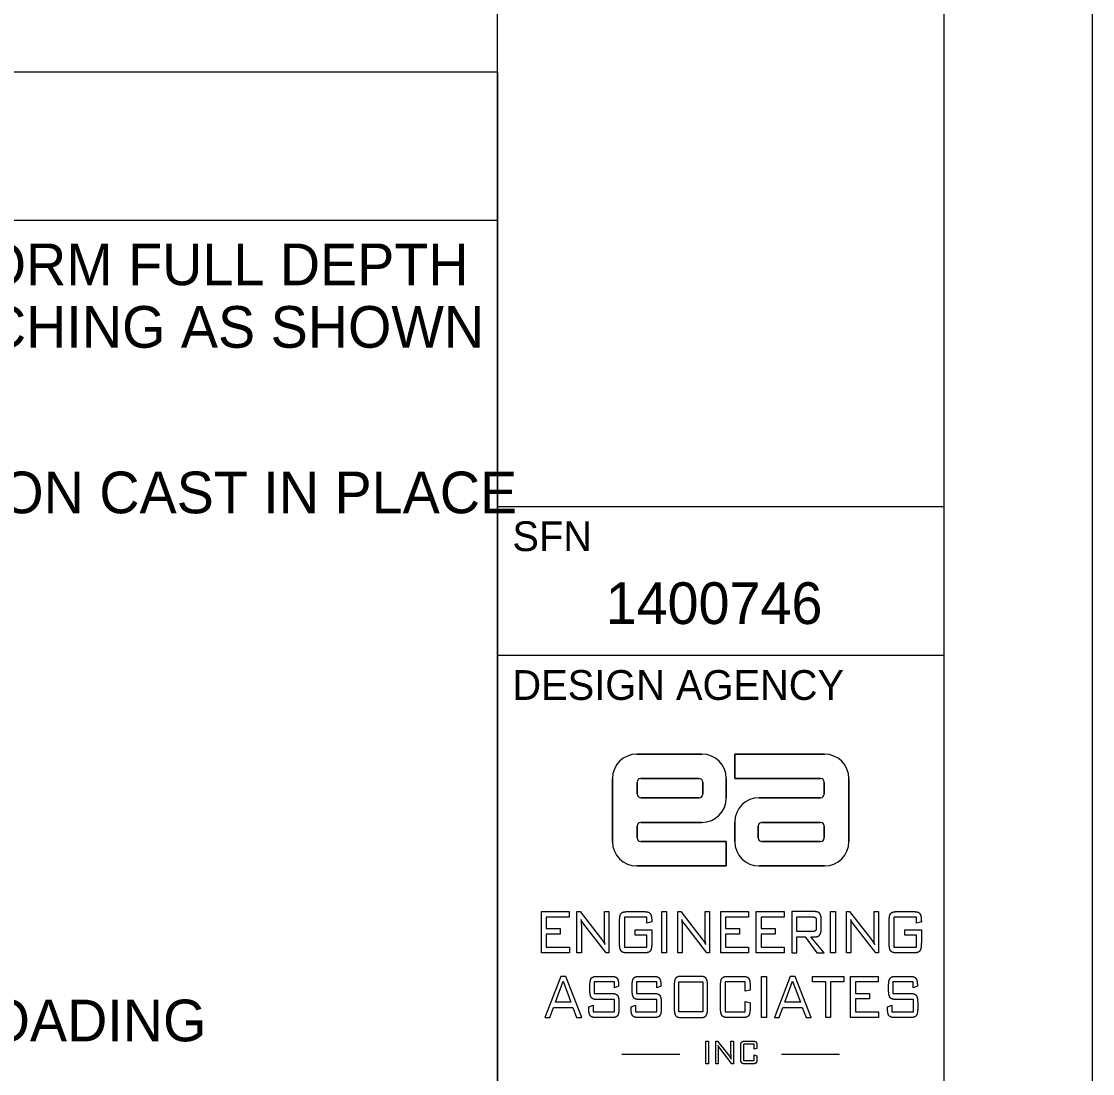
# Model space of a CAD drawing. Extents: x 0 to 680, y -49 to 440.
# Drawn here: x 608 to 680, y 71.9 to 142.6 of the extents above; entities that cross this region are included whole.
import ezdxf

# ---------------------------------------------------------------- set-up
doc = ezdxf.new("R2010")
doc.units = 0
for name, color, linetype in [('SN_X_Public', 7, 'Continuous'), ('SV_X_Shot_Marker', 7, 'Continuous'), ('UT_X_Misc_Cells', 7, 'Continuous'), ('UT_X_Telecom_Cells', 7, 'Continuous'), ('VG_X_Cells', 7, 'Continuous')]:
    doc.layers.add(name, color=color, linetype=linetype)

msp = doc.modelspace()

# ---------------------------------------------------------------- linework, layer by layer
at = {"layer": 'SV_X_Shot_Marker'}
for p, q in [((640, 10), (640, 430)), ((640, 110), (670, 110)), ((640, 100), (670, 100))]:
    msp.add_line(p, q, dxfattribs=at)
msp.add_lwpolyline([(30, 430), (670, 430), (670, 10), (30, 10)], close=True, dxfattribs=at)
at = {"layer": 'UT_X_Misc_Cells'}
for p, q in [((640, 129.205), (495, 129.205)), ((655, 80), (655, 80))]:
    msp.add_line(p, q, dxfattribs=at)
msp.add_lwpolyline([(495, 139.205), (640, 139.205), (640, 13.27), (495, 13.27)], close=True, dxfattribs=at)
at = {"layer": 'UT_X_Telecom_Cells'}
for p, q in [((653.737, 93.354), (649.367, 93.354)), ((649.367, 93.354), (653.737, 93.354)), ((655.947, 93.354), (661.978, 93.354)), ((655.947, 91.713), (655.947, 93.354)), ((647.726, 91.713), (647.726, 87.482)), ((647.726, 87.482), (647.726, 91.713)), ((649.387, 90.665), (649.387, 91.475)), ((649.387, 91.475), (649.387, 90.665)), ((649.624, 91.713), (653.559, 91.713)), ((653.559, 91.713), (649.624, 91.713)), ((653.797, 91.475), (653.797, 90.665)), ((653.797, 90.665), (653.797, 91.475)), ((655.378, 90.408), (655.378, 91.713)), ((655.378, 91.713), (655.378, 90.408)), ((661.721, 91.713), (655.947, 91.713)), ((661.958, 91.475), (661.958, 90.665)), ((661.958, 90.665), (661.958, 91.475)), ((663.619, 87.482), (663.619, 91.713)), ((663.619, 91.713), (663.619, 87.482)), ((653.559, 90.428), (649.624, 90.428)), ((649.624, 90.428), (653.559, 90.428)), ((661.721, 90.428), (657.588, 90.428)), ((657.588, 90.428), (661.721, 90.428)), ((649.624, 88.767), (653.737, 88.767)), ((653.737, 88.767), (649.624, 88.767)), ((655.947, 88.786), (655.947, 87.482)), ((655.947, 87.482), (655.947, 88.786)), ((657.766, 88.767), (661.721, 88.767)), ((661.721, 88.767), (657.766, 88.767)), ((649.387, 87.719), (649.387, 88.529)), ((649.387, 88.529), (649.387, 87.719)), ((657.529, 87.719), (657.529, 88.529)), ((657.529, 88.529), (657.529, 87.719)), ((661.958, 88.529), (661.958, 87.719)), ((661.958, 87.719), (661.958, 88.529)), ((649.624, 87.482), (655.378, 87.482)), ((655.378, 87.482), (655.378, 85.84)), ((661.721, 87.482), (657.766, 87.482)), ((657.766, 87.482), (661.721, 87.482)), ((655.378, 85.84), (649.367, 85.84)), ((657.588, 85.84), (661.978, 85.84)), ((661.978, 85.84), (657.588, 85.84)), ((648.203, 80.655), (648.203, 82.113)), ((648.658, 82.768), (649.911, 82.768)), ((661.43, 82.124), (661.43, 81.72)), ((661.758, 81.612), (661.758, 82.232)), ((666.325, 80.655), (666.325, 82.113)), ((666.78, 82.768), (668.034, 82.768)), ((649.911, 80), (648.658, 80)), ((668.034, 80), (666.78, 80)), ((646.656, 78.418), (647.686, 78.418)), ((649.501, 78.418), (650.531, 78.418)), ((653.669, 78.418), (652.329, 78.418)), ((655.445, 78.418), (656.528, 78.418)), ((666.739, 78.418), (667.769, 78.418)), ((646.205, 77.523), (646.205, 77.764)), ((649.049, 77.523), (649.049, 77.764)), ((651.874, 77.764), (651.874, 76.305)), ((654.12, 76.305), (654.12, 77.764)), ((654.99, 76.305), (654.99, 77.764)), ((666.288, 77.523), (666.288, 77.764)), ((648.164, 76.616), (648.164, 76.305)), ((651.008, 76.616), (651.008, 76.305)), ((668.246, 76.616), (668.246, 76.305)), ((647.714, 75.65), (646.585, 75.65)), ((650.558, 75.65), (649.429, 75.65)), ((652.329, 75.65), (653.669, 75.65)), ((656.528, 75.65), (655.445, 75.65)), ((667.796, 75.65), (666.668, 75.65)), ((656.347, 72.906), (656.347, 73.709)), ((656.597, 74.069), (657.193, 74.069)), ((648.359, 73.19), (652.263, 73.19)), ((659.08, 73.19), (662.985, 73.19)), ((657.193, 72.546), (656.597, 72.546))]:
    msp.add_line(p, q, dxfattribs=at)
for points in [[(661.978, 93.354), (655.947, 93.354), (655.947, 91.713), (661.721, 91.713)], [(649.367, 85.84), (655.378, 85.84), (655.378, 87.482), (649.624, 87.482)], [(645.638, 81.631), (645.638, 80), (645.342, 80), (645.342, 82.768), (645.545, 82.768), (646.995, 80.917)], [(647.186, 81.249), (647.186, 82.768), (647.482, 82.768), (647.482, 80), (647.3, 80), (645.812, 81.925)], [(650.366, 82.145), (650.366, 82.076), (650.043, 81.985), (650.043, 82.391), (648.526, 82.391), (648.526, 80.385), (650.043, 80.385), (650.043, 81.198), (649.26, 81.198), (649.26, 81.551), (650.366, 81.551), (650.366, 80.655)], [(652.408, 81.631), (652.408, 80), (652.112, 80), (652.112, 82.768), (652.315, 82.768), (653.765, 80.917)], [(653.956, 81.249), (653.956, 82.768), (654.252, 82.768), (654.252, 80), (654.071, 80), (652.582, 81.925)], [(661.347, 82.768), (659.786, 82.768), (659.786, 80), (660.111, 80), (660.111, 81.078), (660.681, 81.078), (661.469, 80), (661.949, 80), (661.063, 81.078), (661.347, 81.078)], [(661.221, 81.436), (660.111, 81.436), (660.111, 82.41), (661.221, 82.41)], [(663.76, 81.631), (663.76, 80), (663.464, 80), (663.464, 82.768), (663.668, 82.768), (665.117, 80.917)], [(665.308, 81.249), (665.308, 82.768), (665.604, 82.768), (665.604, 80), (665.423, 80), (663.935, 81.925)], [(668.489, 82.145), (668.489, 82.076), (668.166, 81.985), (668.166, 82.391), (666.648, 82.391), (666.648, 80.385), (668.166, 80.385), (668.166, 81.198), (667.382, 81.198), (667.382, 81.551), (668.489, 81.551), (668.489, 80.655)], [(648.141, 77.811), (648.141, 77.753), (647.864, 77.64), (647.864, 78.042), (646.496, 78.042), (646.496, 77.269), (647.714, 77.269)], [(650.985, 77.811), (650.985, 77.753), (650.708, 77.64), (650.708, 78.042), (649.34, 78.042), (649.34, 77.269), (650.558, 77.269)], [(656.979, 77.764), (656.979, 77.503), (656.654, 77.416), (656.654, 78.042), (655.313, 78.042), (655.313, 76.035), (656.654, 76.035), (656.654, 76.729), (656.979, 76.632), (656.979, 76.305)], [(668.223, 77.811), (668.223, 77.753), (667.946, 77.64), (667.946, 78.042), (666.578, 78.042), (666.578, 77.269), (667.796, 77.269)], [(646.131, 76.305), (646.131, 76.381), (646.431, 76.48), (646.431, 76.035), (647.873, 76.035), (647.873, 76.868), (646.656, 76.868)], [(648.975, 76.305), (648.975, 76.381), (649.275, 76.48), (649.275, 76.035), (650.717, 76.035), (650.717, 76.868), (649.501, 76.868)], [(666.213, 76.305), (666.213, 76.381), (666.513, 76.48), (666.513, 76.035), (667.956, 76.035), (667.956, 76.868), (666.739, 76.868)], [(654.842, 73.443), (654.842, 72.546), (654.68, 72.546), (654.68, 74.069), (654.791, 74.069), (655.589, 73.05)], [(655.694, 73.233), (655.694, 74.069), (655.857, 74.069), (655.857, 72.546), (655.757, 72.546), (654.938, 73.605)], [(657.441, 73.709), (657.441, 73.565), (657.262, 73.518), (657.262, 73.861), (656.525, 73.861), (656.525, 72.758), (657.262, 72.758), (657.262, 73.139), (657.441, 73.086), (657.441, 72.906)]]:
    msp.add_lwpolyline(points, dxfattribs=at)
for points in [[(642.948, 80), (642.948, 82.768), (644.813, 82.768), (644.813, 82.397), (643.273, 82.397), (643.273, 81.627), (644.215, 81.627), (644.215, 81.261), (643.273, 81.261), (643.273, 80.379), (644.829, 80.379), (644.829, 80)], [(651.039, 80), (651.039, 82.768), (651.364, 82.768), (651.364, 80)], [(655, 80), (655, 82.768), (656.865, 82.768), (656.865, 82.397), (655.325, 82.397), (655.325, 81.627), (656.267, 81.627), (656.267, 81.261), (655.325, 81.261), (655.325, 80.379), (656.88, 80.379), (656.88, 80)], [(657.393, 80), (657.393, 82.768), (659.258, 82.768), (659.258, 82.397), (657.718, 82.397), (657.718, 81.627), (658.66, 81.627), (658.66, 81.261), (657.718, 81.261), (657.718, 80.379), (659.273, 80.379), (659.273, 80)], [(662.391, 80), (662.391, 82.768), (662.716, 82.768), (662.716, 80)], [(643.191, 75.65), (643.51, 75.65), (643.757, 76.333), (645.068, 76.333), (645.315, 75.65), (645.671, 75.65), (644.595, 78.418), (644.249, 78.418)], [(643.893, 76.685), (644.413, 78.101), (644.936, 76.685)], [(652.197, 76.035), (652.197, 78.042), (653.801, 78.042), (653.801, 76.035)], [(657.746, 75.65), (657.746, 78.418), (658.071, 78.418), (658.071, 75.65)], [(658.611, 75.65), (658.93, 75.65), (659.177, 76.333), (660.488, 76.333), (660.736, 75.65), (661.091, 75.65), (660.015, 78.418), (659.669, 78.418)], [(659.313, 76.685), (659.834, 78.101), (660.356, 76.685)], [(662.384, 78.042), (662.384, 75.65), (662.061, 75.65), (662.061, 78.042), (661.176, 78.042), (661.176, 78.418), (663.272, 78.418), (663.272, 78.042)], [(663.732, 75.65), (663.732, 78.418), (665.597, 78.418), (665.597, 78.047), (664.057, 78.047), (664.057, 77.277), (664.999, 77.277), (664.999, 76.911), (664.057, 76.911), (664.057, 76.03), (665.612, 76.03), (665.612, 75.65)], [(653.996, 72.546), (653.996, 74.069), (654.175, 74.069), (654.175, 72.546)]]:
    msp.add_lwpolyline(points, close=True, dxfattribs=at)
for centre, radius, start, end in [((649.367, 91.713), 1.641, 90, 180), ((649.367, 91.713), 1.641, 90, 180), ((653.737, 91.713), 1.641, 0, 90), ((653.737, 91.713), 1.641, 0, 90), ((661.978, 91.713), 1.641, 0, 90), ((661.978, 91.713), 1.641, 0, 90), ((649.624, 91.475), 0.237, 90, 180), ((649.624, 91.475), 0.237, 90, 180), ((653.559, 91.475), 0.237, 0, 90), ((653.559, 91.475), 0.237, 0, 90), ((661.721, 91.475), 0.237, 0, 90), ((661.721, 91.475), 0.237, 0, 90), ((649.624, 90.665), 0.237, 180, 270), ((649.624, 90.665), 0.237, 180, 270), ((653.559, 90.665), 0.237, 270, 0), ((653.559, 90.665), 0.237, 270, 0), ((653.737, 90.408), 1.641, 270, 360), ((653.737, 90.408), 1.641, 270, 360), ((657.588, 88.786), 1.641, 90, 180), ((657.588, 88.786), 1.641, 90, 180), ((661.721, 90.665), 0.237, 270, 0), ((661.721, 90.665), 0.237, 270, 0), ((649.624, 88.529), 0.237, 90, 180), ((649.624, 88.529), 0.237, 90, 180), ((657.766, 88.529), 0.237, 90, 180), ((657.766, 88.529), 0.237, 90, 180), ((661.721, 88.529), 0.237, 0, 90), ((661.721, 88.529), 0.237, 0, 90), ((649.367, 87.482), 1.641, 180, 270), ((649.367, 87.482), 1.641, 180, 270), ((649.624, 87.719), 0.237, 180, 270), ((649.624, 87.719), 0.237, 180, 270), ((657.588, 87.482), 1.641, 180, 270), ((657.588, 87.482), 1.641, 180, 270), ((657.766, 87.719), 0.237, 180, 270), ((657.766, 87.719), 0.237, 180, 270), ((661.721, 87.719), 0.237, 270, 0), ((661.721, 87.719), 0.237, 270, 0), ((661.978, 87.482), 1.641, 270, 360), ((661.978, 87.482), 1.641, 270, 360)]:
    msp.add_arc(centre, radius, start, end, dxfattribs=at)
for points in [[(645.779, 81.967), (645.669, 82.108), (645.616, 82.236)], [(645.616, 82.236), (645.627, 82.111), (645.632, 81.968)], [(648.203, 82.113), (648.203, 82.49), (648.297, 82.629)], [(648.297, 82.629), (648.392, 82.768), (648.658, 82.768)], [(649.911, 82.768), (650.172, 82.768), (650.269, 82.633)], [(650.269, 82.633), (650.366, 82.498), (650.366, 82.145)], [(652.549, 81.967), (652.439, 82.108), (652.386, 82.236)], [(652.386, 82.236), (652.397, 82.111), (652.403, 81.968)], [(661.221, 82.41), (661.34, 82.41), (661.385, 82.346)], [(661.662, 82.641), (661.566, 82.768), (661.347, 82.768)], [(661.385, 82.346), (661.43, 82.282), (661.43, 82.124)], [(661.758, 82.232), (661.758, 82.514), (661.662, 82.641)], [(663.902, 81.967), (663.792, 82.108), (663.738, 82.236)], [(663.738, 82.236), (663.749, 82.111), (663.755, 81.968)], [(666.325, 82.113), (666.325, 82.49), (666.42, 82.629)], [(666.42, 82.629), (666.514, 82.768), (666.78, 82.768)], [(668.034, 82.768), (668.294, 82.768), (668.391, 82.633)], [(668.391, 82.633), (668.489, 82.498), (668.489, 82.145)], [(645.632, 81.968), (645.638, 81.825), (645.638, 81.631)], [(645.812, 81.925), (645.801, 81.938), (645.779, 81.967)], [(652.403, 81.968), (652.408, 81.825), (652.408, 81.631)], [(652.582, 81.925), (652.571, 81.938), (652.549, 81.967)], [(661.386, 81.499), (661.342, 81.436), (661.221, 81.436)], [(661.43, 81.72), (661.43, 81.562), (661.386, 81.499)], [(661.662, 81.205), (661.758, 81.332), (661.758, 81.612)], [(663.755, 81.968), (663.76, 81.825), (663.76, 81.631)], [(663.935, 81.925), (663.924, 81.938), (663.902, 81.967)], [(646.995, 80.917), (647.044, 80.854), (647.1, 80.765)], [(647.1, 80.765), (647.156, 80.676), (647.215, 80.568)], [(647.193, 80.847), (647.186, 80.992), (647.186, 81.249)], [(647.215, 80.568), (647.2, 80.702), (647.193, 80.847)], [(648.297, 80.139), (648.203, 80.278), (648.203, 80.655)], [(650.366, 80.655), (650.366, 80.275), (650.271, 80.138)], [(653.765, 80.917), (653.815, 80.854), (653.871, 80.765)], [(653.871, 80.765), (653.927, 80.676), (653.985, 80.568)], [(653.963, 80.847), (653.956, 80.992), (653.956, 81.249)], [(653.985, 80.568), (653.971, 80.702), (653.963, 80.847)], [(661.347, 81.078), (661.566, 81.078), (661.662, 81.205)], [(665.117, 80.917), (665.167, 80.854), (665.223, 80.765)], [(665.223, 80.765), (665.279, 80.676), (665.337, 80.568)], [(665.315, 80.847), (665.308, 80.992), (665.308, 81.249)], [(665.337, 80.568), (665.323, 80.702), (665.315, 80.847)], [(666.42, 80.139), (666.325, 80.278), (666.325, 80.655)], [(668.489, 80.655), (668.489, 80.275), (668.393, 80.138)], [(648.658, 80), (648.392, 80), (648.297, 80.139)], [(650.271, 80.138), (650.175, 80), (649.911, 80)], [(666.78, 80), (666.514, 80), (666.42, 80.139)], [(668.393, 80.138), (668.298, 80), (668.034, 80)], [(646.205, 77.764), (646.205, 78.143), (646.299, 78.281)], [(646.299, 78.281), (646.392, 78.418), (646.656, 78.418)], [(647.686, 78.418), (647.945, 78.418), (648.043, 78.283)], [(648.043, 78.283), (648.141, 78.149), (648.141, 77.811)], [(649.049, 77.764), (649.049, 78.143), (649.143, 78.281)], [(649.143, 78.281), (649.236, 78.418), (649.501, 78.418)], [(650.531, 78.418), (650.789, 78.418), (650.887, 78.283)], [(650.887, 78.283), (650.985, 78.149), (650.985, 77.811)], [(651.969, 78.28), (651.874, 78.141), (651.874, 77.764)], [(652.329, 78.418), (652.063, 78.418), (651.969, 78.28)], [(654.025, 78.281), (653.931, 78.418), (653.669, 78.418)], [(654.12, 77.764), (654.12, 78.143), (654.025, 78.281)], [(654.99, 77.764), (654.99, 78.144), (655.085, 78.281)], [(655.085, 78.281), (655.181, 78.418), (655.445, 78.418)], [(656.528, 78.418), (656.792, 78.418), (656.886, 78.282)], [(656.886, 78.282), (656.979, 78.146), (656.979, 77.764)], [(666.288, 77.764), (666.288, 78.143), (666.381, 78.281)], [(666.381, 78.281), (666.475, 78.418), (666.739, 78.418)], [(667.769, 78.418), (668.027, 78.418), (668.125, 78.283)], [(668.125, 78.283), (668.223, 78.149), (668.223, 77.811)], [(646.299, 77.005), (646.205, 77.143), (646.205, 77.523)], [(647.714, 77.269), (647.973, 77.269), (648.068, 77.133)], [(648.068, 77.133), (648.164, 76.996), (648.164, 76.616)], [(649.143, 77.005), (649.049, 77.143), (649.049, 77.523)], [(650.558, 77.269), (650.817, 77.269), (650.912, 77.133)], [(650.912, 77.133), (651.008, 76.996), (651.008, 76.616)], [(666.381, 77.005), (666.288, 77.143), (666.288, 77.523)], [(667.796, 77.269), (668.055, 77.269), (668.151, 77.133)], [(668.151, 77.133), (668.246, 76.996), (668.246, 76.616)], [(646.656, 76.868), (646.392, 76.868), (646.299, 77.005)], [(649.501, 76.868), (649.236, 76.868), (649.143, 77.005)], [(666.739, 76.868), (666.475, 76.868), (666.381, 77.005)], [(646.226, 75.788), (646.131, 75.925), (646.131, 76.305)], [(646.585, 75.65), (646.321, 75.65), (646.226, 75.788)], [(648.07, 75.786), (647.976, 75.65), (647.714, 75.65)], [(648.164, 76.305), (648.164, 75.923), (648.07, 75.786)], [(649.07, 75.788), (648.975, 75.925), (648.975, 76.305)], [(649.429, 75.65), (649.165, 75.65), (649.07, 75.788)], [(650.914, 75.786), (650.821, 75.65), (650.558, 75.65)], [(651.008, 76.305), (651.008, 75.923), (650.914, 75.786)], [(651.874, 76.305), (651.874, 75.928), (651.969, 75.789)], [(651.969, 75.789), (652.063, 75.65), (652.329, 75.65)], [(653.669, 75.65), (653.931, 75.65), (654.025, 75.786)], [(654.025, 75.786), (654.12, 75.923), (654.12, 76.305)], [(655.085, 75.788), (654.99, 75.925), (654.99, 76.305)], [(655.445, 75.65), (655.181, 75.65), (655.085, 75.788)], [(656.886, 75.786), (656.792, 75.65), (656.528, 75.65)], [(656.979, 76.305), (656.979, 75.922), (656.886, 75.786)], [(666.308, 75.788), (666.213, 75.925), (666.213, 76.305)], [(666.668, 75.65), (666.404, 75.65), (666.308, 75.788)], [(668.153, 75.786), (668.059, 75.65), (667.796, 75.65)], [(668.246, 76.305), (668.246, 75.923), (668.153, 75.786)], [(654.92, 73.628), (654.86, 73.706), (654.83, 73.776)], [(654.83, 73.776), (654.836, 73.707), (654.839, 73.629)], [(654.839, 73.629), (654.842, 73.55), (654.842, 73.443)], [(654.938, 73.605), (654.932, 73.612), (654.92, 73.628)], [(656.347, 73.709), (656.347, 73.917), (656.399, 73.993)], [(656.399, 73.993), (656.452, 74.069), (656.597, 74.069)], [(657.193, 74.069), (657.338, 74.069), (657.39, 73.994)], [(657.39, 73.994), (657.441, 73.919), (657.441, 73.709)], [(655.589, 73.05), (655.616, 73.016), (655.647, 72.967)], [(655.647, 72.967), (655.678, 72.918), (655.71, 72.859)], [(655.698, 73.012), (655.694, 73.092), (655.694, 73.233)], [(655.71, 72.859), (655.702, 72.932), (655.698, 73.012)], [(656.399, 72.622), (656.347, 72.697), (656.347, 72.906)], [(657.441, 72.906), (657.441, 72.696), (657.39, 72.621)], [(656.597, 72.546), (656.452, 72.546), (656.399, 72.622)], [(657.39, 72.621), (657.338, 72.546), (657.193, 72.546)]]:
    msp.add_open_spline(points, degree=2, dxfattribs=at)
at = {"layer": 'VG_X_Cells'}
msp.add_lwpolyline([(0, 0), (680, 0), (680, 440), (0, 440)], close=True, dxfattribs=at)

# ---------------------------------------------------------------- texts
at = {"layer": 'SN_X_Public'}
for s, p in [('CONSTRUCT COMPOSITE DECK. PREFORM FULL DEPTH ', (534.873, 124.866)), ('SUPERSTRUCTURE REPAIRS AND PATCHING AS SHOWN ', (534.873, 120.666)), ('REINFORCED CONCRETE THREE SIDED CULVERT ON CAST IN PLACE ', (514, 109.54)), ('1400746', (647.265, 102.1)), ('HS20-44 (CASE II) AND ALTERNATE MILITARY LOADING ', (520.557, 74.054))]:
    msp.add_text(s, height=2.8, dxfattribs=at).set_placement(p)
at = {"layer": 'UT_X_Misc_Cells'}
for s, p in [('SFN', (641, 107)), ('DESIGN AGENCY', (641, 97))]:
    msp.add_text(s, height=2, dxfattribs=at).set_placement(p)

doc.saveas('drawing.dxf')
